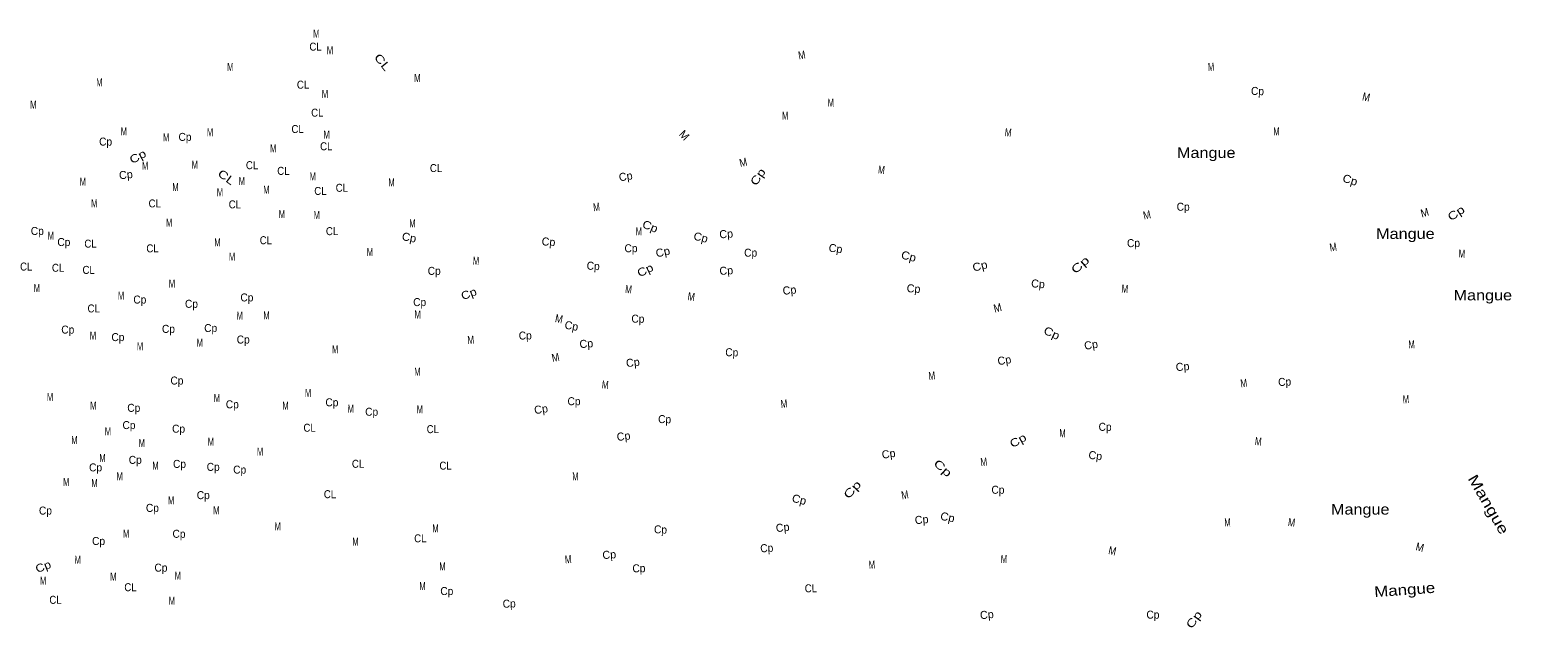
# Model space of a CAD drawing. Extents: x 713577 to 726626, y 7177731 to 7191794.
# Drawn here: x 719267 to 726305, y 7177731 to 7180570 of the extents above; entities that cross this region are included whole.
import ezdxf
from ezdxf.enums import TextEntityAlignment as Align

# ---------------------------------------------------------------- set-up
doc = ezdxf.new("R2010")
doc.units = 0
doc.header["$LTSCALE"] = 15
doc.layers.add('19', color=7, linetype='Continuous')

msp = doc.modelspace()

# ---------------------------------------------------------------- texts
at = {"layer": '19'}
for s, height, rotation, width, p in [('CL', 38, 359.99, 0.9, (720624.78, 7180470.52)), ('M', 38, 359.99, 0.65, (720628.28, 7180532.39)), ('M', 38, 359.99, 0.65, (720693.42, 7180453.73)), ('CL', 38, 308.899, 1.35, (720927.95, 7180403.73)), ('M', 38, 10.027, 0.8, (722937.73, 7180431.14)), ('M', 38, 359.99, 0.65, (720219.88, 7180374.51)), ('M', 38, 2.002, 0.7, (724879, 7180374.62)), ('M', 38, 359.99, 0.65, (719598.05, 7180301.36)), ('CL', 38, 359.99, 0.9, (720565.52, 7180289.87)), ('M', 38, 359.99, 0.65, (721108.36, 7180321.04)), ('Cp', 38, 357.552, 0.95, (725098.14, 7180259.75)), ('M', 38, 359.99, 0.65, (719284.43, 7180194.47)), ('M', 38, 359.99, 0.65, (720669.69, 7180245.76)), ('M', 38, 2.414, 0.7, (723073.18, 7180204.32)), ('M', 38, 347.604, 0.85, (725611.33, 7180231.7)), ('CL', 38, 359.99, 0.9, (720633.28, 7180156.92)), ('M', 38, 0.588, 0.65, (722855.58, 7180142.98)), ('M', 38, 359.99, 0.65, (719714.17, 7180068.23)), ('Cp', 38, 359.99, 0.95, (720004.74, 7180041.85)), ('M', 38, 359.99, 0.65, (720123.73, 7180063.88)), ('CL', 38, 359.99, 0.9, (720539.48, 7180079.27)), ('M', 38, 359.99, 0.65, (720677.56, 7180053.25)), ('M', 38, 353.166, 0.75, (723912.38, 7180062.97)), ('M', 38, 1.821, 0.7, (725189.69, 7180068.33)), ('Cp', 38, 359.99, 0.95, (719627.62, 7180019.54)), ('M', 38, 359.99, 0.65, (719915.23, 7180039.24)), ('M', 38, 359.99, 0.65, (720423.83, 7179987.48)), ('CL', 38, 359.99, 0.9, (720675.71, 7179997.31)), ('Cp', 38, 28.679, 1.25, (719789.64, 7179950.82)), ('M', 38, 359.99, 0.65, (719815.5, 7179904.99)), ('M', 38, 359.99, 0.65, (720051.11, 7179909.56)), ('CL', 38, 359.99, 0.9, (720323.25, 7179907.54)), ('M', 38, 12.504, 0.85, (722660.14, 7179921.7)), ('CL', 38, 323.537, 1.3, (720190.29, 7179854.23)), ('M', 38, 359.99, 0.65, (720274.74, 7179832.52)), ('CL', 38, 359.99, 0.9, (720471.99, 7179880.53)), ('M', 38, 359.99, 0.65, (720611.38, 7179853.85)), ('CL', 38, 359.99, 0.9, (721197.26, 7179893.89)), ('Cp', 38, 56.25, 1.3, (722741.52, 7179860.36)), ('M', 38, 353.494, 0.75, (723310.9, 7179885.83)), ('Cp', 38, 341.968, 1.1, (725533.19, 7179838.63)), ('M', 38, 359.99, 0.65, (719519.65, 7179829.69)), ('M', 38, 359.99, 0.65, (719959.48, 7179803.28)), ('M', 38, 359.99, 0.65, (720170.74, 7179779.23)), ('M', 38, 359.99, 0.65, (720391.22, 7179791.03)), ('CL', 38, 359.99, 0.9, (720648.03, 7179785.06)), ('CL', 38, 359.99, 0.9, (720749.71, 7179800.18)), ('M', 38, 359.99, 0.65, (720985.86, 7179825.81)), ('M', 38, 359.99, 0.65, (719573.8, 7179726.68)), ('CL', 38, 359.99, 0.9, (719861.08, 7179725.97)), ('CL', 38, 359.99, 0.9, (720241.61, 7179721.3)), ('CL', 38, 359.99, 0.9, (720241.61, 7179721.3)), ('M', 38, 5.826, 0.75, (721961.05, 7179709.16)), ('M', 38, 359.99, 0.65, (719929.51, 7179635.13)), ('M', 38, 359.99, 0.65, (720464.91, 7179674.86)), ('M', 38, 359.99, 0.65, (720630.43, 7179670.55)), ('M', 38, 359.99, 0.65, (721084.87, 7179631.31)), ('Cp', 38, 337.611, 1.15, (722207.25, 7179618.33)), ('M', 38, 12.529, 0.85, (724577.63, 7179671.82)), ('M', 38, 15.315, 0.9, (725897.89, 7179682.82)), ('Cp', 38, 33.811, 1.3, (726052.7, 7179683.09)), ('Cp', 38, 359.99, 0.95, (719303.28, 7179595.1)), ('M', 38, 359.99, 0.65, (719367.44, 7179573.37)), ('CL', 38, 359.99, 0.9, (720389.01, 7179551.14)), ('CL', 38, 359.99, 0.9, (720703.28, 7179594.19)), ('Cp', 38, 348.342, 1.05, (721065.69, 7179564.81)), ('M', 38, 359.93, 0.65, (722160.32, 7179592.79)), ('Cp', 38, 345.964, 1.05, (722450.18, 7179565.29)), ('Cp', 38, 359.99, 0.95, (719429.3, 7179542.42)), ('CL', 38, 359.99, 0.9, (719555.99, 7179534.83)), ('CL', 38, 359.99, 0.9, (719850.51, 7179512.41)), ('M', 38, 359.99, 0.65, (720158.85, 7179541.31)), ('M', 38, 359.99, 0.65, (720883.13, 7179495.11)), ('Cp', 38, 0.568, 0.95, (722123.33, 7179513)), ('Cp', 38, 13.194, 1.05, (722278.35, 7179495.67)), ('Cp', 38, 0.386, 0.95, (722691.74, 7179491.87)), ('Cp', 38, 345.445, 1.1, (723437.59, 7179475.46)), ('Cp', 38, 1.711, 0.95, (724510.51, 7179537.66)), ('M', 38, 9.328, 0.8, (725461.12, 7179518.69)), ('M', 38, 355.723, 0.75, (726067.85, 7179487.3)), ('CL', 38, 359.99, 0.9, (719250.6, 7179425.96)), ('CL', 38, 359.99, 0.9, (719401.97, 7179420.34)), ('CL', 38, 359.99, 0.9, (719547.09, 7179410.12)), ('M', 38, 359.99, 0.65, (720228.27, 7179472.19)), ('M', 38, 358.623, 0.7, (721386.67, 7179453.38)), ('Cp', 38, 356.908, 0.95, (721942.69, 7179429.14)), ('Cp', 38, 26.565, 1.2, (722199.01, 7179410.85)), ('Cp', 38, 15.004, 1.1, (723785.41, 7179429.5)), ('Cp', 38, 40.989, 1.45, (724268.86, 7179438.68)), ('M', 38, 359.99, 0.65, (719942.95, 7179345.22)), ('Cp', 38, 359.988, 0.95, (721188.37, 7179405.5)), ('M', 38, 359.99, 0.65, (719301.26, 7179323.62)), ('M', 38, 359.99, 0.65, (719701.07, 7179287.68)), ('Cp', 38, 359.99, 0.95, (719790.25, 7179269.23)), ('Cp', 38, 359.99, 0.95, (720298.66, 7179279.34)), ('Cp', 38, 21.016, 1.15, (721359.56, 7179298.33)), ('M', 38, 353.979, 0.75, (722109.67, 7179318.33)), ('M', 38, 351.575, 0.8, (722406.86, 7179283.55)), ('M', 38, 355.081, 0.75, (724467.14, 7179320.64)), ('CL', 38, 359.99, 0.9, (719571.08, 7179227.15)), ('Cp', 38, 359.99, 0.95, (720035.4, 7179249.12)), ('Cp', 38, 359.99, 0.95, (721119.36, 7179257.15)), ('M', 38, 359.99, 0.65, (721109.81, 7179198.25)), ('M', 38, 14.043, 0.9, (723868.83, 7179231.08)), ('Cp', 38, 359.99, 0.95, (719447.99, 7179126.48)), ('Cp', 38, 359.99, 0.95, (719926.13, 7179130.01)), ('Cp', 38, 359.99, 0.95, (720126.86, 7179133.93)), ('M', 38, 359.99, 0.65, (720264.75, 7179193.46)), ('M', 38, 359.99, 0.65, (720391.77, 7179193.77)), ('M', 38, 348.75, 0.85, (721777.76, 7179178.21)), ('Cp', 38, 358.597, 0.95, (722155.44, 7179178.23)), ('M', 38, 359.99, 0.65, (719567.76, 7179098.15)), ('Cp', 38, 359.99, 0.95, (719686.23, 7179090.89)), ('M', 38, 359.99, 0.65, (720074.86, 7179064.17)), ('Cp', 38, 359.99, 0.95, (720281.19, 7179079.27)), ('M', 38, 4.816, 0.75, (721363.86, 7179077.89)), ('Cp', 38, 0.869, 0.95, (721621.11, 7179098.32)), ('Cp', 38, 334.454, 1.2, (724113.77, 7179111.93)), ('M', 38, 3.232, 0.7, (725831.95, 7179056.61)), ('M', 38, 359.99, 0.65, (719791.19, 7179047.11)), ('M', 38, 359.99, 0.65, (720717.85, 7179033.13)), ('M', 38, 11.547, 0.85, (721768.44, 7178994.86)), ('Cp', 38, 358.114, 0.95, (722601.32, 7179018.65)), ('M', 38, 359.99, 0.65, (721108.44, 7178926.77)), ('Cp', 38, 359.99, 0.95, (719966.56, 7178884.52)), ('M', 38, 354.753, 0.75, (721999.19, 7178864.92)), ('M', 38, 5.639, 0.75, (723554.04, 7178907.59)), ('M', 38, 7.037, 0.75, (725035.93, 7178872.64)), ('Cp', 38, 2.97, 0.95, (725228.8, 7178878.69)), ('M', 38, 359.99, 0.65, (719363.69, 7178805.65)), ('M', 38, 359.99, 0.65, (720156.42, 7178801.56)), ('M', 38, 359.99, 0.65, (720589.28, 7178825.9)), ('Cp', 38, 359.99, 0.95, (720702.47, 7178781.13)), ('M', 38, 6.102, 0.75, (722852.09, 7178774.61)), ('M', 38, 1.864, 0.7, (725804.52, 7178795.98)), ('M', 38, 359.99, 0.65, (719569.35, 7178765.79)), ('Cp', 38, 359.99, 0.95, (719761.53, 7178754.9)), ('Cp', 38, 359.99, 0.95, (720229.47, 7178771.6)), ('M', 38, 359.99, 0.65, (720482.32, 7178765.37)), ('M', 38, 359.99, 0.65, (720791.97, 7178750.84)), ('Cp', 38, 359.99, 0.95, (720891.35, 7178736.34)), ('M', 38, 359.99, 0.65, (721120.05, 7178747.82)), ('M', 38, 359.99, 0.65, (719638.76, 7178642.71)), ('Cp', 38, 359.99, 0.95, (719738.81, 7178672.97)), ('Cp', 38, 359.99, 0.95, (719974.42, 7178655.81)), ('CL', 38, 359.99, 0.9, (720596.49, 7178660.38)), ('CL', 38, 359.99, 0.9, (721181.9, 7178653.69)), ('Cp', 38, 358.498, 0.95, (722282.44, 7178701.06)), ('M', 38, 358.367, 0.7, (724172, 7178634.36)), ('M', 38, 359.99, 0.65, (719479.49, 7178601.6)), ('M', 38, 359.99, 0.65, (719799.67, 7178588.05)), ('M', 38, 359.99, 0.65, (720127.55, 7178593.99)), ('Cp', 38, 29.735, 1.25, (723970.63, 7178602.31)), ('M', 38, 354.195, 0.75, (725100.79, 7178595.73)), ('M', 38, 359.99, 0.65, (719612.74, 7178517.01)), ('Cp', 38, 359.99, 0.95, (719768.39, 7178507.77)), ('M', 38, 359.99, 0.65, (720361.18, 7178546.56)), ('M', 38, 6.567, 0.75, (723801.13, 7178498.37)), ('Cp', 38, 359.99, 0.95, (719580.16, 7178471.93)), ('M', 38, 359.99, 0.65, (719694.34, 7178429.79)), ('M', 38, 359.99, 0.65, (719864.6, 7178480.5)), ('Cp', 38, 359.99, 0.95, (719978.67, 7178488.64)), ('Cp', 38, 359.99, 0.95, (720138.59, 7178474.47)), ('Cp', 38, 359.99, 0.95, (720264.62, 7178461.28)), ('CL', 38, 359.99, 0.9, (720826.81, 7178489.22)), ('CL', 38, 359.99, 0.9, (721242.42, 7178480.26)), ('M', 38, 0.991, 0.7, (721859.34, 7178429.14)), ('Cp', 38, 317.65, 1.45, (723591.63, 7178473.53)), ('M', 38, 359.99, 0.65, (719440.62, 7178403.18)), ('M', 38, 359.99, 0.65, (719574.88, 7178397.56)), ('Cp', 38, 47.584, 1.45, (723188.13, 7178372.77)), ('Cp', 38, 359.968, 0.95, (723865.99, 7178365.75)), ('Mangue', 50, 300.162, 1.3, (726174.78, 7178302.67)), ('M', 38, 359.99, 0.65, (719938.94, 7178315.63)), ('Cp', 38, 359.99, 0.95, (720091.51, 7178340.21)), ('CL', 38, 359.99, 0.9, (720693.51, 7178344.78)), ('Cp', 38, 345.681, 1.05, (722917.52, 7178320.09)), ('M', 38, 10.071, 0.8, (723427.32, 7178342.01)), ('Cp', 38, 359.99, 0.95, (719341.88, 7178266.96)), ('Cp', 38, 359.99, 0.95, (719849.96, 7178279.71)), ('M', 38, 359.99, 0.65, (720153.49, 7178268.2)), ('Cp', 38, 348.36, 1.05, (723623.07, 7178236.06)), ('M', 38, 2.484, 0.7, (724957.19, 7178211.09)), ('M', 38, 352.651, 0.8, (725258.65, 7178210.95)), ('M', 38, 359.99, 0.65, (719725.29, 7178157.85)), ('Cp', 38, 359.99, 0.95, (719976.3, 7178156.61)), ('M', 38, 359.99, 0.65, (720445.03, 7178192.46)), ('M', 38, 359.99, 0.65, (721194.65, 7178181.8)), ('Cp', 38, 357.571, 0.95, (722262.61, 7178177.08)), ('Cp', 38, 359.99, 0.95, (719594.25, 7178122.46)), ('M', 38, 359.99, 0.65, (720814.56, 7178119.67)), ('CL', 38, 359.99, 0.9, (721122.58, 7178135.09)), ('Cp', 38, 3.368, 0.95, (722769.06, 7178088.83)), ('M', 38, 348.102, 0.85, (724405.78, 7178076.25)), ('M', 38, 346.331, 0.9, (725865.94, 7178093.48)), ('Cp', 38, 21.422, 1.15, (719338.14, 7178002.37)), ('M', 38, 359.99, 0.65, (719495.28, 7178033.4)), ('M', 38, 359.99, 0.65, (721227.53, 7178001.47)), ('M', 38, 4.869, 0.75, (721826.48, 7178035.48)), ('M', 38, 3.425, 0.7, (723268.68, 7178010.12)), ('M', 38, 358.424, 0.7, (723893.92, 7178036.71)), ('M', 38, 359.99, 0.65, (719330.91, 7177934.02)), ('M', 38, 359.99, 0.65, (719664.43, 7177952.27)), ('Cp', 38, 359.99, 0.95, (719890.51, 7177995.78)), ('M', 38, 359.99, 0.65, (719970.47, 7177957.92)), ('Cp', 38, 0.926, 0.95, (722161.01, 7177992.79)), ('CL', 38, 359.99, 0.9, (719745.84, 7177902.84)), ('M', 38, 359.99, 0.65, (721132.74, 7177908.03)), ('Cp', 38, 359.99, 0.95, (721248.24, 7177884.64)), ('CL', 38, 0.576, 0.9, (722977.8, 7177897.78)), ('CL', 38, 359.99, 0.9, (719389.76, 7177843.02)), ('M', 38, 359.99, 0.65, (719942.55, 7177838.18)), ('Cp', 38, 1.831, 0.95, (721545.05, 7177824.99)), ('Cp', 38, 359.988, 0.95, (724602.13, 7177772.59)), ('Cp', 38, 54.443, 1.35, (724812.53, 7177757.04))]:
    msp.add_text(s, height=height, rotation=rotation, dxfattribs=dict(at, width=width)).set_placement(p, align=Align.CENTER)
for s, rotation, p in [('M', 313.958, (722362.5, 7180055.51)), ('Cp', 6.361, (719725.91, 7179862.58)), ('Cp', 9.436, (722100.85, 7179854.69)), ('Cp', 4.369, (722576.63, 7179581.07)), ('Cp', 355.926, (721730.17, 7179543.93)), ('Cp', 352.126, (723092.48, 7179512.14)), ('Cp', 3.95, (722576.86, 7179407.11)), ('Cp', 355.233, (724054.93, 7179344.29)), ('Cp', 6.463, (722877.87, 7179314.15)), ('Cp', 355.877, (723464.12, 7179321.56)), ('Cp', 349.55, (721837.37, 7179144.83)), ('Cp', 4.914, (721912.56, 7179059.88)), ('Cp', 10.161, (724311.37, 7179054.59)), ('Cp', 6.758, (722134.13, 7178970.74)), ('Cp', 9.466, (723899.51, 7178981.42)), ('Cp', 5.378, (724744.8, 7178950.86)), ('Cp', 9.335, (721698.74, 7178748.69)), ('Cp', 7.222, (722089.99, 7178620.21)), ('Cp', 9.356, (723349.66, 7178536.65)), ('Cp', 352.618, (724326.46, 7178528.46)), ('Cp', 5.896, (723505.36, 7178223.92)), ('Cp', 6.688, (722845.51, 7178186.89)), ('Cp', 3.933, (722021.14, 7178057.59)), ('Cp', 6.218, (723815.26, 7177772.77))]:
    msp.add_text(s, height=38, rotation=rotation, dxfattribs=at).set_placement(p, align=Align.CENTER)
for s, height, width, p in [('Mangue', 50, 1.15, (724855.48, 7179960.96)), ('Cp', 38, 0.95, (724745.78, 7179710.13)), ('Mangue', 50, 1.15, (725801.32, 7179576.34)), ('Mangue', 50, 1.15, (726169.14, 7179284.38)), ('Cp', 38, 0.95, (721852.45, 7178786.33)), ('Cp', 38, 0.95, (724374.97, 7178664.73)), ('Mangue', 50, 1.15, (725586.85, 7178266.88))]:
    msp.add_text(s, height=height, dxfattribs=dict(at, width=width)).set_placement(p, align=Align.CENTER)
at = {"layer": '19', "width": 1.2}
msp.add_text('Mangue', height=50, rotation=4.122, dxfattribs=at).set_placement((725655.11, 7177874.86))

doc.saveas('drawing.dxf')
